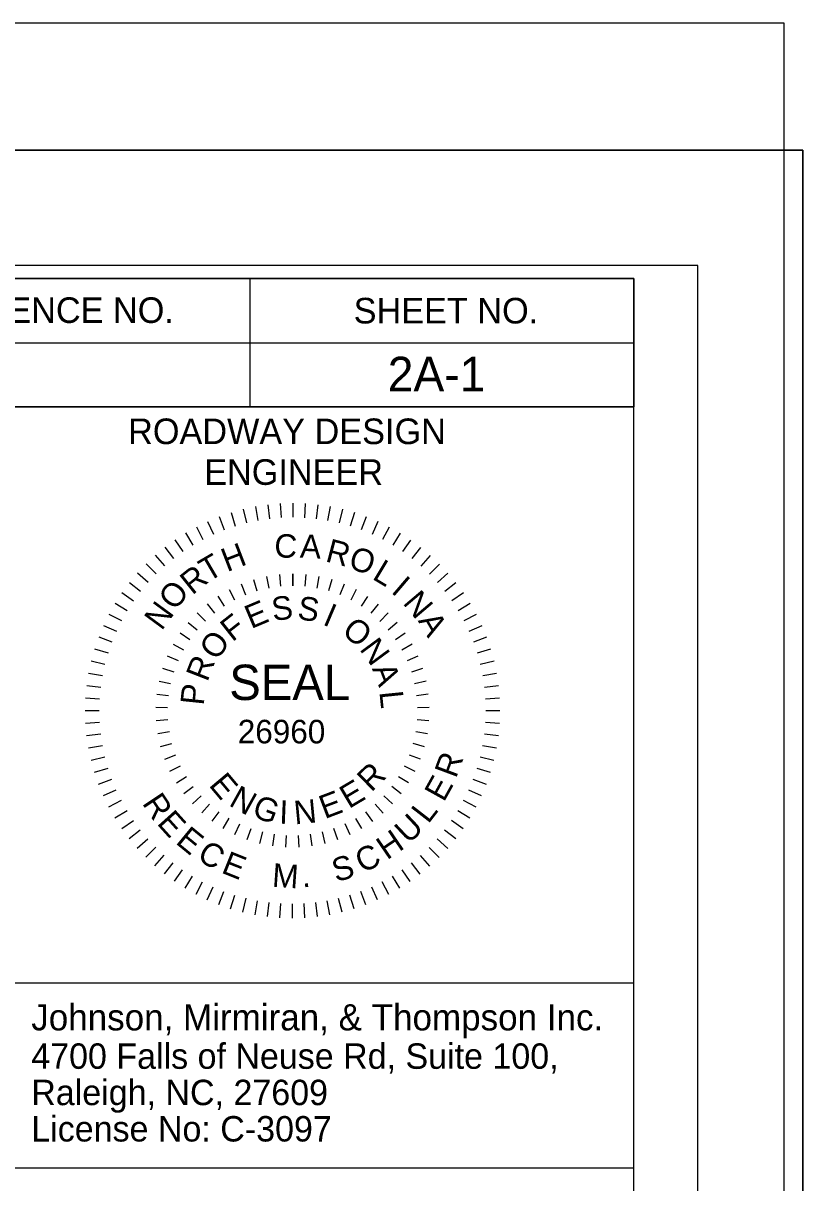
# Model space of a CAD drawing. Extents: x 2294342 to 2294901, y 719427 to 719941.
# Drawn here: x 2294764.08 to 2294794.52, y 719895.86 to 719941.13 of the extents above; entities that cross this region are included whole.
import ezdxf

# ---------------------------------------------------------------- set-up
doc = ezdxf.new("R2010")
doc.units = 0
for name, color, linetype in [('Default', 7, 'Continuous'), ('Raster_Level_2', 7, 'Continuous'), ('Sheet Data Field CELL', 7, 'Continuous'), ('Sheet Plan CELL', 7, 'Continuous'), ('Sheet Plot Border Inside CELL', 7, 'Continuous'), ('Sheet Plot Border Outside CELL', 7, 'Continuous'), ('Sheet Typical CELL', 7, 'Continuous')]:
    doc.layers.add(name, color=color, linetype=linetype)

msp = doc.modelspace()

# ---------------------------------------------------------------- linework, layer by layer
at = {"layer": 'Default'}
for p, q in [((2294454.524, 719936.169), (2294794.524, 719936.169)), ((2294794.524, 719936.169), (2294794.524, 719716.169)), ((2294773.629, 719922.335), (2294773.695, 719921.787)), ((2294774.116, 719922.379), (2294774.149, 719921.828)), ((2294774.605, 719922.393), (2294774.605, 719921.841)), ((2294775.095, 719922.378), (2294775.061, 719921.827)), ((2294775.582, 719922.333), (2294775.515, 719921.785)), ((2294771.733, 719921.87), (2294771.928, 719921.353)), ((2294772.195, 719922.029), (2294772.359, 719921.501)), ((2294772.667, 719922.16), (2294772.798, 719921.624)), ((2294773.145, 719922.262), (2294773.244, 719921.719)), ((2294776.065, 719922.259), (2294775.966, 719921.717)), ((2294776.543, 719922.156), (2294776.412, 719921.62)), ((2294777.015, 719922.025), (2294776.851, 719921.497)), ((2294777.477, 719921.865), (2294777.28, 719921.348)), ((2294770.84, 719921.469), (2294771.096, 719920.98)), ((2294771.281, 719921.682), (2294771.506, 719921.179)), ((2294777.929, 719921.676), (2294777.702, 719921.173)), ((2294778.369, 719921.462), (2294778.112, 719920.973)), ((2294770.003, 719920.963), (2294770.316, 719920.509)), ((2294770.413, 719921.229), (2294770.699, 719920.756)), ((2294778.795, 719921.221), (2294778.508, 719920.749)), ((2294779.206, 719920.955), (2294778.891, 719920.501)), ((2294769.609, 719920.674), (2294769.948, 719920.239)), ((2294779.599, 719920.665), (2294779.259, 719920.231)), ((2294768.876, 719920.026), (2294769.266, 719919.635)), ((2294769.232, 719920.361), (2294769.598, 719919.947)), ((2294779.975, 719920.351), (2294779.608, 719919.938)), ((2294780.331, 719920.015), (2294779.94, 719919.625)), ((2294768.54, 719919.67), (2294768.953, 719919.304)), ((2294774.087, 719919.607), (2294774.131, 719919.149)), ((2294774.603, 719919.631), (2294774.602, 719919.172)), ((2294774.602, 719919.172), (2294774.603, 719919.631)), ((2294775.118, 719919.606), (2294775.074, 719919.148)), ((2294780.666, 719919.659), (2294780.252, 719919.293)), ((2294768.226, 719919.294), (2294768.66, 719918.954)), ((2294772.589, 719919.24), (2294772.762, 719918.813)), ((2294773.076, 719919.41), (2294773.207, 719918.969)), ((2294773.577, 719919.533), (2294773.665, 719919.081)), ((2294775.628, 719919.531), (2294775.54, 719919.08)), ((2294776.129, 719919.408), (2294775.997, 719918.966)), ((2294776.616, 719919.236), (2294776.442, 719918.81)), ((2294780.979, 719919.282), (2294780.544, 719918.943)), ((2294767.936, 719918.901), (2294768.39, 719918.587)), ((2294771.676, 719918.762), (2294771.928, 719918.376)), ((2294772.121, 719919.022), (2294772.334, 719918.615)), ((2294777.083, 719919.018), (2294776.87, 719918.611)), ((2294777.528, 719918.756), (2294777.275, 719918.371)), ((2294781.268, 719918.888), (2294780.814, 719918.575)), ((2294767.67, 719918.49), (2294768.142, 719918.204)), ((2294771.258, 719918.458), (2294771.547, 719918.099)), ((2294777.945, 719918.452), (2294777.656, 719918.093)), ((2294781.534, 719918.478), (2294781.061, 719918.192)), ((2294767.429, 719918.064), (2294767.918, 719917.807)), ((2294770.873, 719918.117), (2294771.194, 719917.787)), ((2294778.33, 719918.11), (2294778.008, 719917.78)), ((2294781.774, 719918.051), (2294781.284, 719917.794)), ((2294767.215, 719917.624), (2294767.718, 719917.398)), ((2294770.207, 719917.33), (2294770.585, 719917.067)), ((2294770.521, 719917.739), (2294770.872, 719917.443)), ((2294778.681, 719917.732), (2294778.33, 719917.436)), ((2294778.995, 719917.322), (2294778.616, 719917.06)), ((2294781.987, 719917.61), (2294781.484, 719917.385)), ((2294767.026, 719917.172), (2294767.543, 719916.976)), ((2294769.935, 719916.892), (2294770.336, 719916.667)), ((2294779.266, 719916.884), (2294778.864, 719916.659)), ((2294782.175, 719917.158), (2294781.658, 719916.963)), ((2294766.866, 719916.71), (2294767.394, 719916.546)), ((2294769.705, 719916.43), (2294770.127, 719916.245)), ((2294779.495, 719916.42), (2294779.072, 719916.237)), ((2294782.334, 719916.696), (2294781.806, 719916.532)), ((2294766.735, 719916.238), (2294767.271, 719916.107)), ((2294769.522, 719915.947), (2294769.96, 719915.805)), ((2294779.677, 719915.938), (2294779.238, 719915.797)), ((2294782.465, 719916.224), (2294781.929, 719916.093)), ((2294766.632, 719915.76), (2294767.174, 719915.661)), ((2294782.567, 719915.746), (2294782.024, 719915.647)), ((2294766.558, 719915.277), (2294767.106, 719915.21)), ((2294769.386, 719915.45), (2294769.835, 719915.35)), ((2294779.812, 719915.44), (2294779.362, 719915.341)), ((2294782.64, 719915.262), (2294782.092, 719915.196)), ((2294766.513, 719914.79), (2294767.064, 719914.756)), ((2294769.299, 719914.941), (2294769.755, 719914.886)), ((2294779.898, 719914.931), (2294779.442, 719914.877)), ((2294782.684, 719914.775), (2294782.133, 719914.742)), ((2294766.498, 719914.301), (2294767.05, 719914.3)), ((2294769.261, 719914.427), (2294769.72, 719914.415)), ((2294779.935, 719914.417), (2294779.476, 719914.406)), ((2294782.698, 719914.286), (2294782.146, 719914.286)), ((2294766.512, 719913.811), (2294767.063, 719913.844)), ((2294769.273, 719913.911), (2294769.731, 719913.944)), ((2294779.922, 719913.901), (2294779.464, 719913.935)), ((2294782.683, 719913.796), (2294782.132, 719913.83)), ((2294766.556, 719913.324), (2294767.104, 719913.39)), ((2294769.335, 719913.399), (2294769.788, 719913.476)), ((2294779.409, 719913.483), (2294779.863, 719913.406)), ((2294782.638, 719913.309), (2294782.09, 719913.376)), ((2294766.629, 719912.84), (2294767.172, 719912.939)), ((2294769.445, 719912.895), (2294769.889, 719913.015)), ((2294779.748, 719912.885), (2294779.304, 719913.007)), ((2294782.564, 719912.826), (2294782.021, 719912.925)), ((2294766.731, 719912.362), (2294767.267, 719912.493)), ((2294769.605, 719912.404), (2294770.035, 719912.567)), ((2294779.588, 719912.395), (2294779.158, 719912.558)), ((2294782.461, 719912.348), (2294781.925, 719912.479)), ((2294766.862, 719911.89), (2294767.39, 719912.054)), ((2294769.811, 719911.932), (2294770.223, 719912.135)), ((2294779.381, 719911.923), (2294778.969, 719912.127)), ((2294782.329, 719911.876), (2294781.802, 719912.04)), ((2294767.021, 719911.428), (2294767.538, 719911.624)), ((2294770.06, 719911.481), (2294770.451, 719911.722)), ((2294779.131, 719911.473), (2294778.74, 719911.715)), ((2294782.169, 719911.414), (2294781.653, 719911.61)), ((2294767.209, 719910.976), (2294767.712, 719911.201)), ((2294770.353, 719911.055), (2294770.719, 719911.334)), ((2294770.685, 719910.661), (2294771.022, 719910.974)), ((2294778.504, 719910.654), (2294778.167, 719910.967)), ((2294778.837, 719911.047), (2294778.471, 719911.327)), ((2294781.981, 719910.962), (2294781.478, 719911.189)), ((2294767.422, 719910.535), (2294767.911, 719910.792)), ((2294771.054, 719910.3), (2294771.36, 719910.645)), ((2294778.135, 719910.294), (2294777.83, 719910.639)), ((2294781.767, 719910.522), (2294781.278, 719910.779)), ((2294767.662, 719910.109), (2294768.135, 719910.394)), ((2294771.456, 719909.977), (2294771.727, 719910.349)), ((2294771.887, 719909.694), (2294772.121, 719910.091)), ((2294777.3, 719909.689), (2294777.067, 719910.086)), ((2294777.732, 719909.971), (2294777.462, 719910.344)), ((2294781.526, 719910.096), (2294781.054, 719910.382)), ((2294767.928, 719909.698), (2294768.382, 719910.011)), ((2294768.217, 719909.304), (2294768.652, 719909.643)), ((2294772.344, 719909.454), (2294772.538, 719909.871)), ((2294772.822, 719909.259), (2294772.975, 719909.693)), ((2294776.365, 719909.255), (2294776.212, 719909.69)), ((2294776.843, 719909.45), (2294776.649, 719909.868)), ((2294780.97, 719909.292), (2294780.535, 719909.632)), ((2294781.26, 719909.685), (2294780.806, 719909.999)), ((2294768.53, 719908.927), (2294768.944, 719909.293)), ((2294773.423, 719909.558), (2294773.312, 719909.111)), ((2294773.822, 719909.011), (2294773.888, 719909.466)), ((2294774.335, 719908.961), (2294774.357, 719909.42)), ((2294774.851, 719908.96), (2294774.83, 719909.42)), ((2294775.364, 719909.01), (2294775.298, 719909.465)), ((2294775.871, 719909.109), (2294775.761, 719909.556)), ((2294780.656, 719908.916), (2294780.243, 719909.283)), ((2294768.865, 719908.571), (2294769.256, 719908.961)), ((2294780.32, 719908.56), (2294779.93, 719908.951)), ((2294769.221, 719908.235), (2294769.587, 719908.648)), ((2294769.597, 719907.921), (2294769.937, 719908.356)), ((2294779.587, 719907.912), (2294779.248, 719908.347)), ((2294779.964, 719908.225), (2294779.598, 719908.639)), ((2294769.99, 719907.631), (2294770.304, 719908.085)), ((2294770.401, 719907.365), (2294770.687, 719907.837)), ((2294778.782, 719907.357), (2294778.497, 719907.83)), ((2294779.193, 719907.623), (2294778.88, 719908.077)), ((2294770.827, 719907.124), (2294771.084, 719907.613)), ((2294771.267, 719906.91), (2294771.493, 719907.413)), ((2294777.915, 719906.904), (2294777.69, 719907.407)), ((2294778.356, 719907.117), (2294778.099, 719907.607)), ((2294771.719, 719906.722), (2294771.915, 719907.238)), ((2294772.18, 719906.561), (2294772.345, 719907.089)), ((2294772.653, 719906.43), (2294772.784, 719906.966)), ((2294776.529, 719906.426), (2294776.398, 719906.962)), ((2294777.001, 719906.557), (2294776.837, 719907.085)), ((2294777.463, 719906.716), (2294777.267, 719907.233)), ((2294773.131, 719906.327), (2294773.23, 719906.87)), ((2294773.614, 719906.253), (2294773.681, 719906.801)), ((2294774.101, 719906.208), (2294774.135, 719906.759)), ((2294774.59, 719906.193), (2294774.591, 719906.745)), ((2294775.08, 719906.207), (2294775.047, 719906.758)), ((2294775.567, 719906.251), (2294775.501, 719906.799)), ((2294776.051, 719906.324), (2294775.952, 719906.867))]:
    msp.add_line(p, q, dxfattribs=at)
msp.add_lwpolyline([(2294454.524, 719936.169), (2294794.524, 719936.169), (2294794.524, 719716.169), (2294454.524, 719716.169)], close=True, dxfattribs=at)
msp.add_lwpolyline([(2294454.524, 719936.169), (2294794.524, 719936.169), (2294794.524, 719716.169), (2294454.524, 719716.169)], close=True, dxfattribs=at)
at = {"layer": 'Raster_Level_2'}
msp.add_lwpolyline([(2294747.917, 719896.44), (2294787.924, 719896.44), (2294787.924, 719903.659), (2294747.917, 719903.659)], close=True, dxfattribs=at)
at = {"layer": 'Sheet Plan CELL'}
msp.add_lwpolyline([(2294787.924, 719903.659), (2294761.64, 719903.659), (2294761.64, 719926.159), (2294787.924, 719926.159)], dxfattribs=at)
at = {"layer": 'Sheet Plot Border Inside CELL'}
msp.add_lwpolyline([(2294790.424, 719931.679), (2294457.124, 719931.679), (2294457.124, 719720.659), (2294790.424, 719720.659)], close=True, dxfattribs=at)
at = {"layer": 'Sheet Plot Border Outside CELL'}
for points in [[(2294793.79, 719941.133), (2294456.99, 719941.133), (2294456.99, 719721.133), (2294793.79, 719721.133)], [(2294794.524, 719936.169), (2294454.524, 719936.169), (2294454.524, 719716.169), (2294794.524, 719716.169)]]:
    msp.add_lwpolyline(points, close=True, dxfattribs=at)
at = {"layer": 'Sheet Typical CELL'}
for p, q in [((2294772.924, 719931.159), (2294772.924, 719926.159)), ((2294747.914, 719928.659), (2294787.924, 719928.659)), ((2294747.914, 719926.159), (2294767.924, 719926.159))]:
    msp.add_line(p, q, dxfattribs=at)
for points in [[(2294787.924, 719931.169), (2294487.924, 719931.169), (2294487.924, 719721.169), (2294787.924, 719721.169)], [(2294747.914, 719931.169), (2294787.924, 719931.169), (2294787.924, 719926.159), (2294747.914, 719926.159)]]:
    msp.add_lwpolyline(points, close=True, dxfattribs=at)

# ---------------------------------------------------------------- texts
at = {"layer": 'Default'}
for s, height, rotation, p in [('C', 0.919, 357.3039, (2294773.868, 719920.286)), ('A', 0.919, 357.3039, (2294774.873, 719920.267)), ('R', 0.919, 345.2946, (2294775.847, 719920.13)), ('H', 0.919, 21.0146, (2294772.037, 719919.697)), ('O', 0.919, 342.2378, (2294776.737, 719919.864)), ('T', 0.919, 30.4466, (2294771.297, 719919.297)), ('L', 0.919, 329.1015, (2294777.672, 719919.454)), ('R', 0.919, 38.6075, (2294770.678, 719918.783)), ('O', 0.919, 51.6643, (2294770.011, 719918.164)), ('I', 0.919, 319.5261, (2294778.413, 719918.92)), ('S', 0.919, 7.5951, (2294773.843, 719917.79)), ('S', 0.919, 352.2989, (2294774.761, 719917.866)), ('N', 0.919, 310.2316, (2294778.874, 719918.486)), ('N', 0.919, 53.6237, (2294769.483, 719917.388)), ('E', 0.919, 22.8914, (2294772.979, 719917.475)), ('I', 0.919, 337.0026, (2294775.738, 719917.666)), ('F', 0.919, 38.1876, (2294772.243, 719916.955)), ('O', 0.919, 321.7064, (2294776.479, 719917.307)), ('A', 0.919, 300.4641, (2294779.48, 719917.806)), ('O', 0.919, 53.4838, (2294771.63, 719916.214)), ('N', 0.919, 306.4101, (2294777.187, 719916.691)), ('R', 0.919, 68.7801, (2294771.266, 719915.389)), ('SEAL', 1.3802, 359.947, (2294772.125, 719914.709)), ('A', 0.919, 291.1139, (2294777.691, 719915.937)), ('P', 0.919, 84.0763, (2294771.126, 719914.478)), ('L', 0.919, 275.8176, (2294777.988, 719915.027)), ('26960', 0.9194, 359.947, (2294772.457, 719913.017)), ('R', 0.919, 69.6194, (2294780.978, 719911.622)), ('E', 0.919, 310.0171, (2294771.3, 719911.376)), ('R', 0.919, 44.5119, (2294777.675, 719911.086)), ('E', 0.919, 30.7408, (2294776.798, 719910.446)), ('E', 0.919, 60.9466, (2294780.504, 719910.694)), ('R', 0.919, 303.882, (2294768.702, 719910.675)), ('N', 0.919, 330.8721, (2294772.071, 719910.609)), ('G', 0.919, 339.6384, (2294772.971, 719910.177)), ('E', 0.919, 20.7549, (2294775.854, 719910.054)), ('I', 0.919, 357.7332, (2294774.066, 719909.881)), ('N', 0.919, 5.3628, (2294774.69, 719909.85)), ('L', 0.919, 52.154, (2294779.895, 719909.847)), ('E', 0.919, 311.9538, (2294769.271, 719909.88)), ('U', 0.919, 43.2714, (2294779.124, 719909.063)), ('E', 0.919, 320.5966, (2294769.995, 719909.13)), ('H', 0.919, 34.3888, (2294778.286, 719908.443)), ('C', 0.919, 329.2691, (2294770.823, 719908.497)), ('E', 0.919, 338.2416, (2294771.776, 719907.978)), ('C', 0.919, 25.5662, (2294777.325, 719907.937)), ('M', 0.919, 356.0369, (2294773.78, 719907.422)), ('S', 0.919, 16.5636, (2294776.297, 719907.589)), ('.', 0.919, 3.7793, (2294774.981, 719907.393))]:
    msp.add_text(s, height=height, rotation=rotation, dxfattribs=at).set_placement(p)
at = {"layer": 'Raster_Level_2'}
for s, height, p in [('Johnson, Mirmiran, & Thompson Inc.', 1.02224, (2294764.393, 719901.81)), ('4700 Falls of Neuse Rd, Suite 100, ', 0.99303, (2294764.393, 719900.31)), ('Raleigh, NC, 27609', 0.99303, (2294764.393, 719898.891)), ('License No: C-3097', 0.99303, (2294764.393, 719897.472))]:
    msp.add_text(s, height=height, dxfattribs=at).set_placement(p)
at = {"layer": 'Sheet Data Field CELL'}
msp.add_text('2A-1', height=1.35, rotation=360, dxfattribs=at).set_placement((2294778.314, 719926.76))
at = {"layer": 'Sheet Plan CELL'}
for s, height, p in [('ROADWAY DESIGN', 1.00002, (2294768.176, 719924.699)), ('ENGINEER', 1, (2294771.146, 719923.109))]:
    msp.add_text(s, height=height, dxfattribs=at).set_placement(p)
at = {"layer": 'Sheet Typical CELL'}
for s, height, p in [('PROJECT REFERENCE NO.', 1.00002, (2294752.354, 719929.429)), ('SHEET NO.', 1, (2294776.984, 719929.409))]:
    msp.add_text(s, height=height, dxfattribs=at).set_placement(p)

doc.saveas('drawing.dxf')
